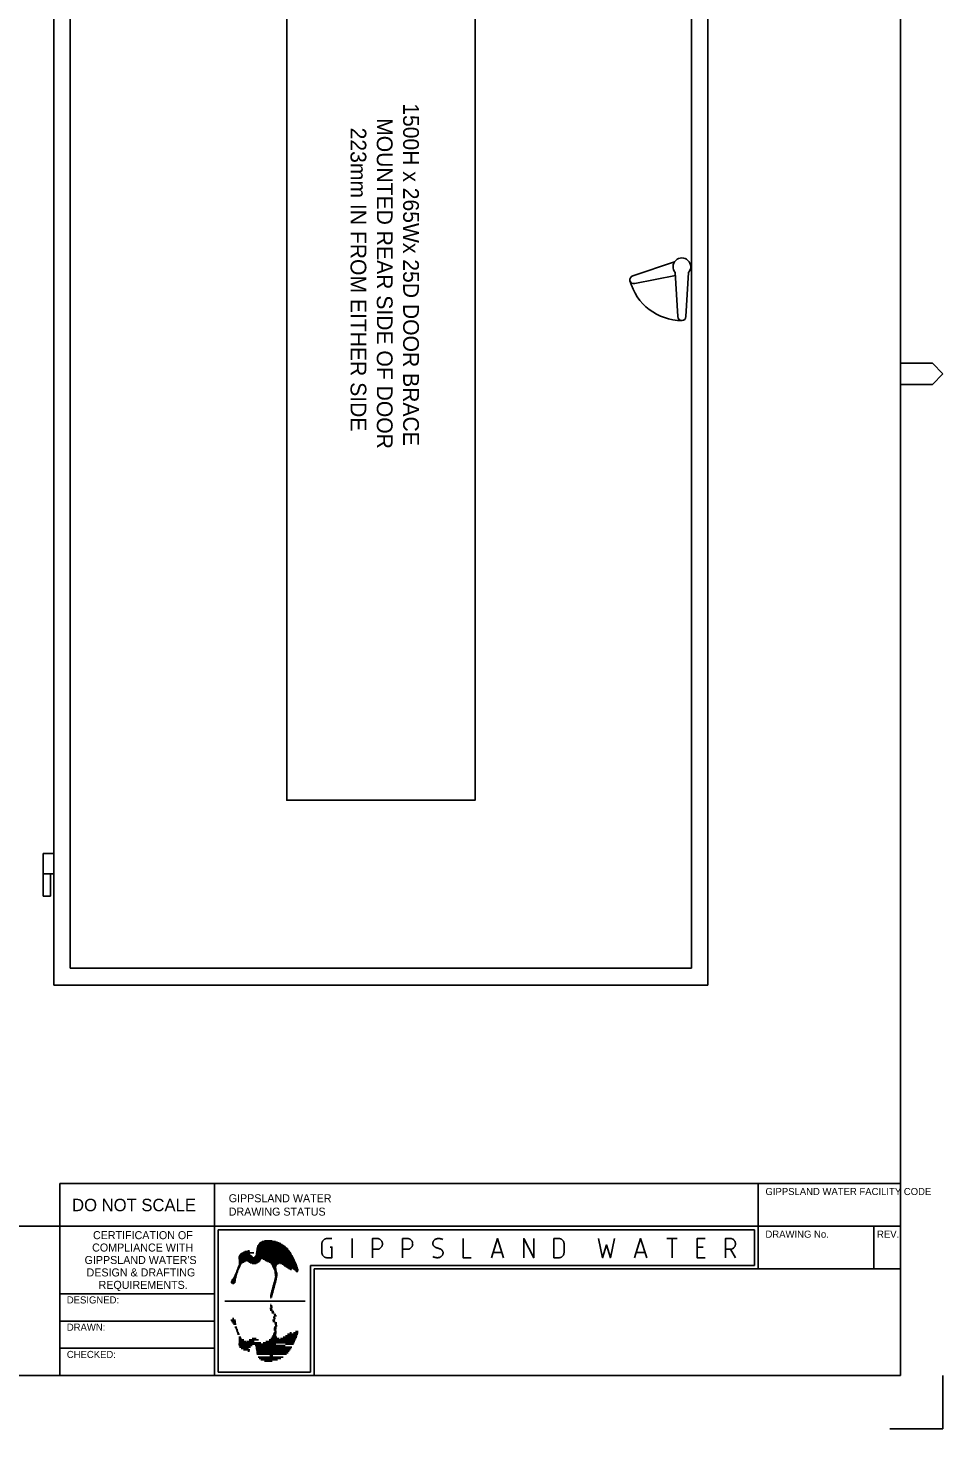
# Model space of a CAD drawing. Extents: x 0 to 4205, y 0 to 2970.
# Drawn here: x 2918 to 4205, y 0 to 1970 of the extents above; entities that cross this region are included whole.
import ezdxf

# ---------------------------------------------------------------- set-up
doc = ezdxf.new("R2010")
doc.units = 0
for name, color, linetype in [('A1BORDER', 7, 'Continuous'), ('BASE', 7, 'Continuous'), ('Level 1', 7, 'Continuous')]:
    doc.layers.add(name, color=color, linetype=linetype)

msp = doc.modelspace()

# ---------------------------------------------------------------- linework, layer by layer
at = {"layer": 'A1BORDER'}
for p, q in [((4145, 2905), (4145, 75)), ((4145, 1498.8), (4190, 1498.8)), ((4190, 1498.8), (4205, 1483.8)), ((4190, 1468.8), (4205, 1483.8)), ((4145, 1468.8), (4190, 1468.8)), ((2962.5, 345), (2962.5, 75)), ((2962.5, 345), (4145, 345)), ((3180, 345), (3180, 75)), ((3945, 225), (3945, 345)), ((140, 285), (4145, 285)), ((3185, 280), (3940, 280)), ((3185, 280), (3185, 80)), ((3940, 230), (3940, 280)), ((4107.5, 225), (4107.5, 285)), ((3240.2, 256.6), (3279.2, 256.6)), ((3240.6, 257.6), (3278, 257.6)), ((3241.2, 258.6), (3276.6, 258.6)), ((3241.9, 259.6), (3275, 259.6)), ((3242.7, 260.6), (3273.2, 260.6)), ((3243.7, 261.6), (3271.2, 261.6)), ((3245.1, 262.6), (3268.8, 262.6)), ((3247, 263.6), (3265.8, 263.6)), ((3250.1, 264.6), (3261, 264.6)), ((3213.7, 240.6), (3291.2, 240.6)), ((3213.7, 239.6), (3291.8, 239.6)), ((3213.8, 241.6), (3234, 241.6)), ((3214, 238.6), (3245.4, 238.6)), ((3214.1, 242.6), (3232.8, 242.6)), ((3214.2, 237.6), (3244.8, 237.6)), ((3214.2, 236.6), (3224.4, 236.6)), ((3214.5, 243.6), (3231.9, 243.6)), ((3215.2, 244.6), (3230.8, 244.6)), ((3216.3, 245.6), (3229.5, 245.6)), ((3217.7, 246.6), (3227.9, 246.6)), ((3219.2, 247.6), (3235.5, 247.6)), ((3220.9, 248.6), (3229.5, 248.6)), ((3222.7, 249.6), (3226.8, 249.6)), ((3225.7, 236.6), (3244.2, 236.6)), ((3226.9, 250.6), (3229.3, 250.6)), ((3236, 241.6), (3290.7, 241.6)), ((3237.1, 242.6), (3290.2, 242.6)), ((3237.7, 243.6), (3289.6, 243.6)), ((3238.1, 244.6), (3289, 244.6)), ((3238.2, 245.6), (3288.4, 245.6)), ((3238.3, 246.6), (3287.9, 246.6)), ((3238.5, 247.6), (3287.2, 247.6)), ((3238.6, 248.6), (3286.6, 248.6)), ((3238.8, 249.6), (3285.9, 249.6)), ((3238.9, 250.6), (3285.1, 250.6)), ((3239.1, 251.6), (3284.3, 251.6)), ((3239.2, 252.6), (3283.5, 252.6)), ((3239.4, 253.6), (3282.5, 253.6)), ((3239.6, 254.6), (3281.5, 254.6)), ((3239.8, 255.6), (3280.4, 255.6)), ((3248.6, 238.6), (3292.2, 238.6)), ((3250.6, 237.6), (3292.8, 237.6)), ((3252.4, 236.6), (3293.2, 236.6)), ((3209.1, 217.6), (3211.8, 217.6)), ((3209.6, 218.6), (3212.1, 218.6)), ((3210, 219.6), (3212.4, 219.6)), ((3210.3, 220.6), (3212.8, 220.6)), ((3210.7, 221.6), (3213.1, 221.6)), ((3211.1, 222.6), (3213.5, 222.6)), ((3211.4, 223.6), (3213.8, 223.6)), ((3211.8, 224.6), (3214.2, 224.6)), ((3212.2, 225.6), (3214.5, 225.6)), ((3212.5, 226.6), (3215, 226.6)), ((3212.9, 227.6), (3215.5, 227.6)), ((3213.2, 228.6), (3216, 228.6)), ((3213.6, 229.6), (3216.5, 229.6)), ((3214, 230.6), (3217, 230.6)), ((3214.2, 231.6), (3217.5, 231.6)), ((3214.4, 235.6), (3222.9, 235.6)), ((3214.4, 234.6), (3221.2, 234.6)), ((3214.4, 233.6), (3219.2, 233.6)), ((3214.4, 232.6), (3218, 232.6)), ((3227.5, 235.6), (3243.4, 235.6)), ((3228.8, 234.6), (3242.1, 234.6)), ((3230.2, 233.6), (3240.6, 233.6)), ((3233.1, 232.6), (3238.4, 232.6)), ((3254.4, 235.6), (3293.7, 235.6)), ((3256.8, 234.6), (3294.1, 234.6)), ((3258.8, 233.6), (3294.5, 233.6)), ((3259.4, 232.6), (3270.8, 232.6)), ((3260, 231.6), (3268.6, 231.6)), ((3260.5, 230.6), (3267.6, 230.6)), ((3261, 229.6), (3267, 229.6)), ((3261.6, 228.6), (3266.7, 228.6)), ((3262.1, 227.6), (3266.6, 227.6)), ((3262.5, 226.6), (3266.7, 226.6)), ((3263, 225.6), (3266.9, 225.6)), ((3263.5, 224.6), (3267.1, 224.6)), ((3263.9, 223.6), (3267.2, 223.6)), ((3264.2, 222.6), (3267.4, 222.6)), ((3264.3, 221.6), (3267.7, 221.6)), ((3264.5, 220.6), (3267.9, 220.6)), ((3264.6, 219.6), (3268.1, 219.6)), ((3264.7, 218.6), (3268.4, 218.6)), ((3264.9, 217.6), (3268.6, 217.6)), ((3272.9, 232.6), (3295, 232.6)), ((3275, 231.6), (3295.4, 231.6)), ((3276.6, 230.6), (3295.7, 230.6)), ((3278.1, 229.6), (3296.1, 229.6)), ((3279.7, 228.6), (3296.5, 228.6)), ((3281.2, 227.6), (3296.8, 227.6)), ((3282.8, 226.6), (3297.1, 226.6)), ((3284.3, 225.6), (3288.7, 225.6)), ((3285.9, 224.6), (3288.4, 224.6)), ((3287.6, 223.6), (3287.7, 223.6)), ((3289.6, 225.6), (3297.4, 225.6)), ((3291, 224.6), (3297.7, 224.6)), ((3292.4, 223.6), (3298, 223.6)), ((3293.8, 222.6), (3297.9, 222.6)), ((3295.1, 221.6), (3297.4, 221.6)), ((3315, 230), (3940, 230)), ((3315, 80), (3315, 230)), ((3320, 225), (4145, 225)), ((3320, 75), (3320, 225)), ((3203.1, 206.6), (3209.4, 206.6)), ((3203.2, 207.6), (3209.7, 207.6)), ((3203.6, 205.6), (3208.7, 205.6)), ((3203.7, 208.6), (3209.8, 208.6)), ((3204.5, 209.6), (3209.9, 209.6)), ((3205.2, 204.6), (3207.2, 204.6)), ((3205.5, 210.6), (3210, 210.6)), ((3206.2, 211.6), (3210.2, 211.6)), ((3206.9, 212.6), (3210.5, 212.6)), ((3207.3, 213.6), (3210.8, 213.6)), ((3207.8, 214.6), (3211, 214.6)), ((3208.2, 215.6), (3211.2, 215.6)), ((3208.7, 216.6), (3211.5, 216.6)), ((3261, 197.6), (3264.1, 197.6)), ((3261.2, 198.6), (3264.4, 198.6)), ((3261.5, 199.6), (3264.7, 199.6)), ((3261.8, 200.6), (3265, 200.6)), ((3262.1, 201.6), (3265.2, 201.6)), ((3262.4, 202.6), (3265.5, 202.6)), ((3262.6, 203.6), (3265.8, 203.6)), ((3262.9, 204.6), (3266, 204.6)), ((3263.2, 205.6), (3266.3, 205.6)), ((3263.4, 206.6), (3266.6, 206.6)), ((3263.7, 207.6), (3266.9, 207.6)), ((3264, 208.6), (3267.1, 208.6)), ((3264.2, 209.6), (3267.2, 209.6)), ((3264.5, 210.6), (3267.5, 210.6)), ((3264.8, 211.6), (3267.7, 211.6)), ((3265, 216.6), (3268.5, 216.6)), ((3265, 212.6), (3267.9, 212.6)), ((3265.1, 215.6), (3268.4, 215.6)), ((3265.2, 214.6), (3268.2, 214.6)), ((3265.2, 213.6), (3268.1, 213.6)), ((3180, 190), (2962.5, 190)), ((3194.7, 179.9), (3307.4, 179.9)), ((3258.2, 187.6), (3261.4, 187.6)), ((3258.2, 186.6), (3261.2, 186.6)), ((3258.2, 185.6), (3260.9, 185.6)), ((3258.6, 188.6), (3261.7, 188.6)), ((3258.8, 189.6), (3262, 189.6)), ((3259, 184.6), (3259.5, 184.6)), ((3259.1, 190.6), (3262.2, 190.6)), ((3259.4, 191.6), (3262.5, 191.6)), ((3259.6, 192.6), (3262.8, 192.6)), ((3259.9, 193.6), (3263.1, 193.6)), ((3260.2, 194.6), (3263.3, 194.6)), ((3260.5, 195.6), (3263.6, 195.6)), ((3260.7, 196.6), (3263.9, 196.6)), ((3257.7, 169.2), (3260.9, 169.2)), ((3258.2, 173.2), (3261.2, 173.2)), ((3258.2, 167.2), (3261.4, 167.2)), ((3258.6, 171.2), (3261.7, 171.2)), ((3259, 175.2), (3259.5, 175.2)), ((3260.2, 165.2), (3263.3, 165.2)), ((3260.7, 163.2), (3263.9, 163.2)), ((3263.3, 161.2), (3266.5, 161.2)), ((3263.9, 159.2), (3267, 159.2)), ((3180, 151.7), (2962.5, 151.7)), ((3203.1, 153.2), (3209.4, 153.2)), ((3203.7, 151.2), (3209.8, 151.2)), ((3205.2, 155.2), (3207.2, 155.2)), ((3205.5, 149.2), (3210, 149.2)), ((3206.9, 147.2), (3210.5, 147.2)), ((3208.7, 143.2), (3211.5, 143.2)), ((3209.6, 141.2), (3212.1, 141.2)), ((3210.3, 139.2), (3212.8, 139.2)), ((3261.7, 153.2), (3264.9, 153.2)), ((3262.2, 151.2), (3265.4, 151.2)), ((3262.4, 157.2), (3265.5, 157.2)), ((3262.9, 155.2), (3266, 155.2)), ((3263.3, 139.2), (3266.8, 139.2)), ((3263.6, 141.2), (3267.2, 141.2)), ((3263.9, 143.2), (3267.3, 143.2)), ((3264.5, 149.2), (3267.5, 149.2)), ((3265, 147.2), (3267.9, 147.2)), ((3265.2, 145.2), (3268.2, 145.2)), ((3211.1, 137.2), (3213.5, 137.2)), ((3211.8, 135.2), (3214.2, 135.2)), ((3212.5, 133.2), (3215, 133.2)), ((3213.7, 119.2), (3266.4, 119.2)), ((3214, 129.2), (3217, 129.2)), ((3214, 121.2), (3245.4, 121.2)), ((3214.2, 123.2), (3224.4, 123.2)), ((3214.4, 127.2), (3218, 127.2)), ((3214.4, 125.2), (3221.2, 125.2)), ((3225.7, 123.2), (3235.9, 123.2)), ((3228.8, 125.2), (3242.1, 125.2)), ((3233.1, 127.2), (3238.4, 127.2)), ((3248.6, 121.2), (3292.2, 121.2)), ((3252.4, 123.2), (3293.2, 123.2)), ((3256.8, 125.2), (3294.1, 125.2)), ((3259.4, 127.2), (3270.8, 127.2)), ((3260.5, 129.2), (3267.6, 129.2)), ((3261.6, 131.2), (3266.7, 131.2)), ((3262.5, 133.2), (3266.7, 133.2)), ((3263.5, 135.2), (3267.1, 135.2)), ((3264.2, 137.2), (3267.4, 137.2)), ((3272.9, 127.2), (3295, 127.2)), ((3276.6, 129.2), (3295.7, 129.2)), ((3279.7, 131.2), (3296.5, 131.2)), ((3279.7, 119.2), (3291.2, 119.2)), ((3282.8, 133.2), (3297.1, 133.2)), ((3285.9, 135.2), (3288.4, 135.2)), ((3291, 135.2), (3297.7, 135.2)), ((3293.8, 137.2), (3297.9, 137.2)), ((3180, 113.4), (2962.5, 113.4)), ((3214.1, 117.2), (3232.8, 117.2)), ((3215.2, 115.2), (3230.8, 115.2)), ((3217.7, 113.2), (3227.9, 113.2)), ((3220.9, 111.2), (3229.5, 111.2)), ((3226.9, 109.2), (3229.3, 109.2)), ((3237.1, 117.2), (3279.5, 117.2)), ((3238.1, 115.2), (3289, 115.2)), ((3238.3, 113.2), (3287.9, 113.2)), ((3238.6, 111.2), (3286.6, 111.2)), ((3238.9, 109.2), (3285.1, 109.2)), ((3239.2, 107.2), (3283.5, 107.2)), ((3239.6, 105.2), (3281.5, 105.2)), ((3241.2, 101.2), (3276.6, 101.2)), ((3242.7, 99.2), (3273.2, 99.2)), ((3257.9, 103.2), (3262.2, 103.2)), ((3315, 80), (3185, 80)), ((3245.1, 97.2), (3268.8, 97.2)), ((3250.1, 95.2), (3261, 95.2)), ((4145, 75), (140, 75)), ((4145, 75), (4145, 75)), ((4205, 0), (4205, 75)), ((4130, 0), (4205, 0))]:
    msp.add_line(p, q, dxfattribs=at)
for points in [[(3342.5, 255.8), (3345.3, 255.8), (3345.3, 240.8), (3338.2, 240.8), (3337.6, 240.8), (3337, 240.9), (3336.4, 241.1), (3335.8, 241.2), (3335.2, 241.5), (3334.7, 241.8), (3334.1, 242.2), (3333.7, 242.6), (3333.2, 243), (3332.8, 243.5), (3332.4, 244), (3332.1, 244.6), (3331.8, 245.1), (3331.6, 245.7), (3331.4, 246.4), (3331.2, 247), (3331.1, 247.6), (3331.1, 248.3), (3331.1, 260.2), (3331.1, 260.9), (3331.2, 261.6), (3331.4, 262.2), (3331.6, 262.8), (3331.8, 263.4), (3332.1, 263.9), (3332.4, 264.5), (3332.8, 265), (3333.2, 265.5), (3333.7, 265.9), (3334.1, 266.4), (3334.7, 266.7), (3335.2, 267), (3335.8, 267.2), (3336.4, 267.4), (3337, 267.6), (3337.6, 267.7), (3338.2, 267.7), (3345.3, 267.7)], [(3373.7, 240.8), (3373.7, 267.7)], [(3402.1, 240.8), (3402.1, 267.7), (3409.2, 267.7), (3409.8, 267.7), (3410.4, 267.6), (3411, 267.4), (3411.6, 267.2), (3412.2, 267), (3412.7, 266.7), (3413.2, 266.4), (3413.7, 265.9), (3414.2, 265.5), (3414.6, 265), (3415, 264.5), (3415.3, 263.9), (3415.6, 263.4), (3415.9, 262.8), (3416.1, 262.2), (3416.2, 261.6), (3416.2, 260.9), (3416.3, 260.2), (3416.2, 259.6), (3416.2, 258.9), (3416.1, 258.3), (3415.9, 257.7), (3415.6, 257.1), (3415.3, 256.5), (3415, 256), (3414.6, 255.5), (3414.2, 255), (3413.7, 254.5), (3413.2, 254.1), (3412.7, 253.8), (3412.2, 253.5), (3411.6, 253.2), (3411, 253), (3410.4, 252.9), (3409.8, 252.8), (3409.2, 252.8), (3402.1, 252.8)], [(3444.7, 240.8), (3444.7, 267.7), (3451.8, 267.7), (3452.4, 267.7), (3453, 267.6), (3453.6, 267.4), (3454.2, 267.2), (3454.7, 267), (3455.2, 266.7), (3455.8, 266.4), (3456.3, 265.9), (3456.8, 265.5), (3457.2, 265), (3457.6, 264.5), (3457.9, 263.9), (3458.2, 263.4), (3458.4, 262.8), (3458.6, 262.2), (3458.8, 261.6), (3458.8, 260.9), (3458.9, 260.2), (3458.8, 259.6), (3458.8, 258.9), (3458.6, 258.3), (3458.4, 257.7), (3458.2, 257.1), (3457.9, 256.5), (3457.6, 256), (3457.2, 255.5), (3456.8, 255), (3456.3, 254.5), (3455.8, 254.1), (3455.2, 253.8), (3454.7, 253.5), (3454.2, 253.2), (3453.6, 253), (3453, 252.9), (3452.4, 252.8), (3451.8, 252.8), (3444.7, 252.8)], [(3487.2, 242.3), (3488.4, 241.8), (3489.5, 241.4), (3490.6, 241.1), (3491.8, 240.9), (3493, 240.8), (3494.2, 240.8), (3494.4, 240.8), (3495.2, 240.9), (3495.9, 241.1), (3496.7, 241.3), (3497.4, 241.6), (3498.1, 242), (3498.6, 242.3), (3499.1, 242.7), (3499.5, 243.1), (3499.9, 243.5), (3500.2, 243.9), (3500.6, 244.4), (3500.9, 245), (3501.1, 245.5), (3501.2, 246.1), (3501.4, 246.6), (3501.5, 246.8), (3501.5, 247.2), (3501.5, 247.6), (3501.5, 248.1), (3501.5, 248.5), (3501.4, 248.9), (3501.2, 249.3), (3501.1, 249.7), (3500.9, 250.1), (3500.7, 250.5), (3500.5, 250.8), (3500.2, 251.1), (3500.1, 251.2), (3499.2, 252), (3498.5, 252.6), (3497.6, 253.1), (3496.7, 253.5), (3495.8, 253.9), (3494.8, 254.2), (3494.4, 254.2), (3493.4, 254.5), (3492.5, 254.8), (3491.5, 255.2), (3490.6, 255.7), (3489.8, 256.3), (3489, 256.9), (3488.7, 257.2), (3488.4, 257.6), (3488.1, 257.9), (3487.9, 258.2), (3487.7, 258.6), (3487.5, 258.9), (3487.4, 259.4), (3487.3, 259.8), (3487.2, 260.2), (3487.2, 260.6), (3487.2, 261.1), (3487.2, 261.4), (3487.2, 261.8), (3487.4, 262.3), (3487.6, 262.9), (3487.8, 263.4), (3488.1, 263.9), (3488.4, 264.4), (3488.7, 264.9), (3489.1, 265.4), (3489.5, 265.8), (3490, 266.2), (3490.1, 266.2), (3490.8, 266.7), (3491.5, 267), (3492.2, 267.2), (3493, 267.5), (3493.8, 267.6), (3494.4, 267.7), (3495.6, 267.8), (3496.8, 267.7), (3497.9, 267.4), (3499.1, 267.2), (3500.2, 266.8), (3501.4, 266.2)], [(3529.8, 267.7), (3529.8, 240.8), (3541.2, 240.8)], [(3569.6, 240.8), (3578.1, 267.7), (3586.6, 240.8)], [(3615, 240.8), (3615, 267.7), (3629.2, 240.8), (3629.2, 267.7)], [(3657.6, 240.8), (3657.6, 267.7), (3664.7, 267.7), (3665.3, 267.7), (3665.9, 267.6), (3666.5, 267.4), (3667.1, 267.2), (3667.7, 267), (3668.2, 266.7), (3668.8, 266.4), (3669.2, 265.9), (3669.7, 265.5), (3670.1, 265), (3670.5, 264.5), (3670.8, 263.9), (3671.1, 263.4), (3671.4, 262.8), (3671.6, 262.2), (3671.7, 261.6), (3671.8, 260.9), (3671.8, 260.2), (3671.8, 248.3), (3671.8, 247.6), (3671.7, 247), (3671.6, 246.4), (3671.4, 245.7), (3671.1, 245.1), (3670.8, 244.6), (3670.5, 244), (3670.1, 243.5), (3669.7, 243), (3669.2, 242.6), (3668.8, 242.2), (3668.2, 241.8), (3667.7, 241.5), (3667.1, 241.2), (3666.5, 241.1), (3665.9, 240.9), (3665.3, 240.8), (3664.7, 240.8), (3657.6, 240.8)], [(3720.1, 267.7), (3725.7, 240.8), (3731.4, 258.8), (3737.1, 240.8), (3742.8, 267.7)], [(3771.1, 240.8), (3779.6, 267.7), (3788.2, 240.8)], [(3816.6, 267.7), (3830.8, 267.7)], [(3823.7, 267.7), (3823.7, 240.8)], [(3870.5, 240.8), (3859.1, 240.8), (3859.1, 267.7), (3870.5, 267.7)], [(3898.9, 240.8), (3898.9, 267.7), (3906, 267.7), (3906.6, 267.7), (3907.2, 267.6), (3907.8, 267.4), (3908.4, 267.2), (3909, 267), (3909.5, 266.7), (3910.1, 266.4), (3910.5, 265.9), (3911, 265.5), (3911.4, 265), (3911.8, 264.5), (3912.1, 263.9), (3912.4, 263.4), (3912.7, 262.8), (3912.8, 262.2), (3913, 261.6), (3913.1, 260.9), (3913.1, 260.2), (3913.1, 259.6), (3913, 258.9), (3912.8, 258.3), (3912.7, 257.7), (3912.4, 257.1), (3912.1, 256.5), (3911.8, 256), (3911.4, 255.5), (3911, 255), (3910.5, 254.5), (3910.1, 254.1), (3909.5, 253.8), (3909, 253.5), (3908.4, 253.2), (3907.8, 253), (3907.2, 252.9), (3906.6, 252.8), (3906, 252.8), (3898.9, 252.8)], [(3572.4, 248.3), (3583.8, 248.3)], [(3774, 248.3), (3785.3, 248.3)], [(3867.7, 255.8), (3859.1, 255.8)], [(3906, 252.8), (3913.1, 240.8)]]:
    msp.add_lwpolyline(points, dxfattribs=at)
at = {"layer": 'Level 1'}
for p, q in [((3827.3, 1641.2), (3768.5, 1621.5)), ((3828.4, 1622.1), (3771.5, 1610.6)), ((3828.1, 1626), (3832, 1564.1)), ((3847.1, 1626), (3843.2, 1564.1)), ((2939.1, 809.1), (2939.1, 749.1)), ((2954.1, 809.1), (2939.1, 809.1)), ((2954.1, 780.4), (2939.1, 780.4)), ((2949.1, 780.4), (2949.1, 749.1)), ((2949.1, 749.1), (2939.1, 749.1))]:
    msp.add_line(p, q, dxfattribs=at)
for points in [[(2954.1, 2644.1), (3874.1, 2644.1), (3874.1, 624.1), (2954.1, 624.1)], [(2977.1, 2620.2), (3851.1, 2620.2), (3851.1, 648.1), (2977.1, 648.1)], [(3281.6, 2384.1), (3546.6, 2384.1), (3546.6, 884.1), (3281.6, 884.1)]]:
    msp.add_lwpolyline(points, close=True, dxfattribs=at)
for centre, radius, start, end in [((3837.6, 1634.1), 12.5, 319.4608, 220.5392), ((3770, 1616), 5.63, 105, 285), ((3837.6, 1634.1), 75.6, 195, 270), ((3837.6, 1564.1), 5.62, 180, 0)]:
    msp.add_arc(centre, radius, start, end, dxfattribs=at)

# ---------------------------------------------------------------- texts
at = {"layer": 'A1BORDER'}
for s, height, p in [('GIPPSLAND WATER FACILITY CODE', 10, (3955.2, 328.9)), ('DO NOT SCALE', 17.5, (2979.6, 306.2)), ('GIPPSLAND WATER', 11.25, (3200, 318.8)), ('DRAWING STATUS', 11.25, (3200, 300)), ('CERTIFICATION OF', 11.25, (3009, 266.9)), ('DRAWING No.', 10, (3955.2, 268.9)), ('REV.', 10, (4112.2, 268.9)), ('COMPLIANCE WITH', 11.25, (3007.8, 249.5)), ("GIPPSLAND WATER'S", 11.25, (2997.2, 232)), ('DESIGN & DRAFTING', 11.25, (3000, 214.5)), ('REQUIREMENTS.', 11.25, (3016.9, 197)), ('DESIGNED:', 10, (2972.2, 176.5)), ('DRAWN:', 10, (2972.2, 138.1)), ('CHECKED:', 10, (2972.2, 99.8))]:
    msp.add_text(s, height=height, dxfattribs=at).set_placement(p)
at = {"layer": 'BASE'}
for s, p in [('1500H x 265Wx 25D DOOR BRACE', (3445.4, 1864.1)), ('MOUNTED REAR SIDE OF DOOR', (3408.4, 1843.1)), ('223mm IN FROM EITHER SIDE', (3371.4, 1829.8))]:
    msp.add_text(s, height=22.198, rotation=270, dxfattribs=at).set_placement(p)

doc.saveas('drawing.dxf')
